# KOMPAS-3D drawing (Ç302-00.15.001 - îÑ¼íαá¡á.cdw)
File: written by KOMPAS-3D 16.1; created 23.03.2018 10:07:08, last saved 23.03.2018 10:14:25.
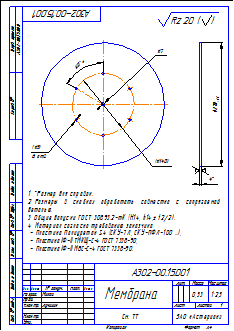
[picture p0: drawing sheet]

Sheet 1: A4, portrait

Title block, sheet 1: name: Мембрана; designation: А302-00.15.001; mass: 0,53; scale: 1:2,5; sheets: 1; organisation: ЗАО «Астерион»; sheet format: A4; stored path: \\192.168.87.28\Konstructor_doc\Мембранные насосы\Мембранный электропривод\А302-00.00.000 - ASTRA-302 (МЭ200)\Чертежи\А302-00.15.001 - Мембрана.cdw; drawn by: Милов; technical control: Лучихин

Views: Вид 1, Спереди, Проекционный вид 2
Referenced files in Z:\Мембранные насосы\Мембранный электропривод\А302-00.00.000 - ASTRA-302 (МЭ200)\3Д\: А302-00.15.001 - Мембрана.m3d
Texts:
  См. ТТ
  *Размер для справок.
  Размеры в скобках обработать совместно с сопрягаемой
  деталью.
  Общие допуски ГОСТ 30893.2-mK (H14, h14,  t2/2).
  Материал согласно требованию заказчика
  - Пластина Полиуретан S4 (СКУ-7Л, СКУ-ПФЛ-100 ...),
  - Пластина  Ф-I  ТМКЩ-C-4 ГОСТ 7338-90,
  - Пластина  Ф- I МБС-С-4 ГОСТ 7338-90.
  Rz 20
  Rz 20 ( )
Dimensions and other numbers on the sheet: 140; 5; 6 отв.; 7; 4; 278; 1:2,5; 1; 0,53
